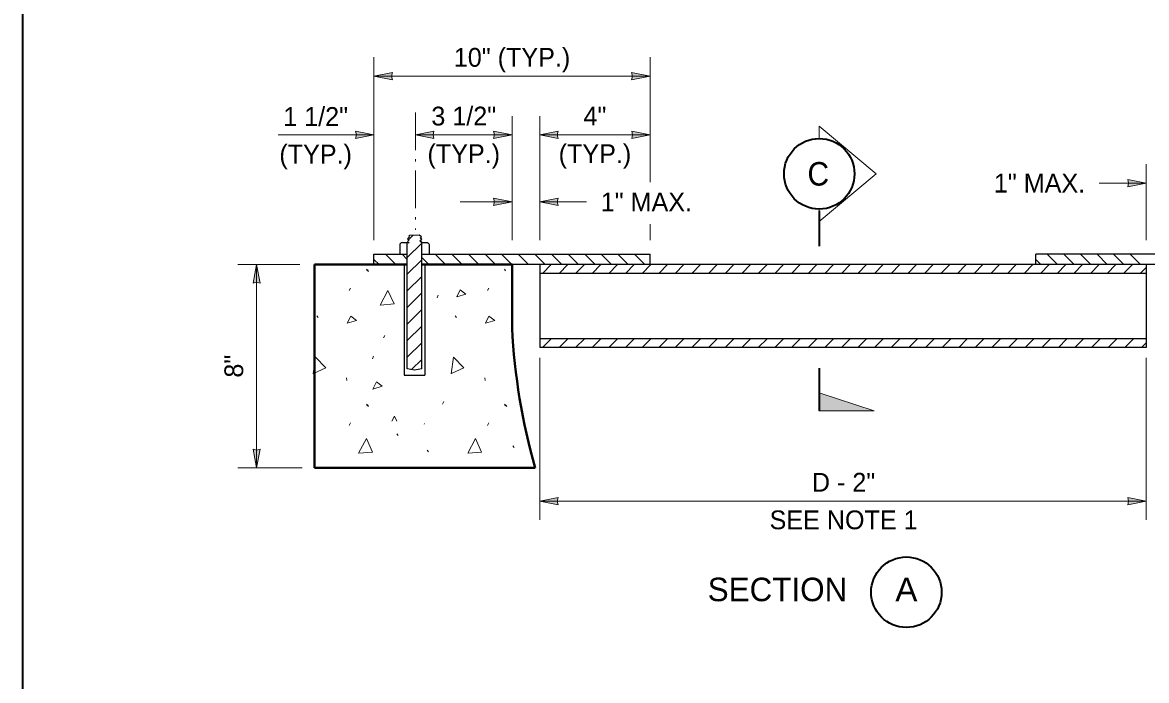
# Model space of a CAD drawing. Extents: x 99860 to 103153, y 99998 to 102077.
# Drawn here: x 99862 to 100819, y 100578 to 101138 of the extents above; entities that cross this region are included whole.
import ezdxf
from ezdxf.enums import TextEntityAlignment as Align

# ---------------------------------------------------------------- set-up
doc = ezdxf.new("R2010")
doc.units = 0
doc.header["$LTSCALE"] = 6.4
doc.linetypes.add('DOT_DASHED', pattern=[7.7, 5, -1.2, 0.3, -1.2])
for name, color, linetype, lineweight in [('1', 7, 'Continuous', 13), ('13', 7, 'Continuous', 40), ('15', 7, 'Continuous', 13), ('17', 7, 'Continuous', 13), ('18', 7, 'Continuous', 13), ('20', 7, 'Continuous', 13), ('9', 7, 'Continuous', 13)]:
    doc.layers.add(name, color=color, linetype=linetype, lineweight=lineweight)

msp = doc.modelspace()

# ---------------------------------------------------------------- hatches: boundary and pattern name
at = {"layer": '15'}
for points in [[(100161.332, 101092.323), (100177.057, 101089.239), (100176.329, 101092.323), (100177.057, 101095.407)], [(100396.492, 101092.323), (100380.767, 101089.239), (100381.495, 101092.323), (100380.767, 101095.407)], [(100161.332, 101042.323), (100145.607, 101039.239), (100146.335, 101042.323), (100145.607, 101045.407)], [(100196.622, 101042.323), (100212.347, 101039.239), (100211.619, 101042.323), (100212.347, 101045.407)], [(100278.942, 101042.323), (100263.217, 101039.239), (100263.945, 101042.323), (100263.217, 101045.407)], [(100302.472, 101042.323), (100318.197, 101039.239), (100317.469, 101042.323), (100318.197, 101045.407)], [(100396.562, 101042.323), (100380.837, 101039.239), (100381.565, 101042.323), (100380.837, 101045.407)], [(100818.992, 101001.29), (100803.267, 100998.206), (100803.995, 101001.29), (100803.267, 101004.374)], [(100278.942, 100985.29), (100263.217, 100982.206), (100263.945, 100985.29), (100263.217, 100988.374)], [(100302.472, 100985.29), (100318.197, 100982.206), (100317.469, 100985.29), (100318.197, 100988.374)], [(100061.397, 100931.954), (100064.481, 100916.229), (100061.397, 100916.957), (100058.313, 100916.229)], [(100061.397, 100759.144), (100058.313, 100774.869), (100061.397, 100774.141), (100064.481, 100774.869)], [(100302.472, 100730.814), (100318.197, 100727.73), (100317.469, 100730.814), (100318.197, 100733.898)], [(100818.992, 100730.814), (100803.267, 100727.73), (100803.995, 100730.814), (100803.267, 100733.898)]]:
    msp.add_hatch(color=256, dxfattribs=at).paths.add_polyline_path(points)
at = {"layer": '9'}
msp.add_hatch(color=256, dxfattribs=at).paths.add_polyline_path([(100540.533, 100822.948), (100587.415, 100807.423), (100540.533, 100807.423)])

# ---------------------------------------------------------------- linework, layer by layer
at = {"layer": '1', "lineweight": 25}
for p, q in [((100191.702, 100956.784), (100191.012, 100956.094)), ((100191.012, 100956.094), (100191.702, 100955.544)), ((100199.872, 100956.924), (100191.702, 100956.784)), ((100183.542, 100940.734), (100183.542, 100949.594)), ((100185.552, 100950.704), (100191.208, 100950.704)), ((100189.702, 100843.193), (100189.702, 100950.704)), ((100201.602, 100950.564), (100202.022, 100950.834)), ((100201.839, 100950.704), (100206.442, 100950.704)), ((100201.982, 100843.193), (100201.982, 100950.704)), ((100208.652, 100940.734), (100208.652, 100948.694)), ((100161.332, 100931.954), (100161.332, 100940.734)), ((100161.332, 100940.734), (100189.702, 100940.734)), ((100186.997, 100931.954), (100186.997, 100837.8)), ((100201.982, 100940.734), (100396.562, 100940.734)), ((100204.637, 100931.954), (100204.637, 100837.8)), ((100842.522, 100931.954), (100278.932, 100931.954)), ((100302.452, 100931.954), (100302.452, 100861.384)), ((100396.562, 100931.954), (100396.562, 100940.734)), ((100724.902, 100931.954), (100724.902, 100940.734)), ((100919.482, 100940.734), (100724.902, 100940.734)), ((100818.992, 100931.954), (100818.992, 100861.384)), ((100818.992, 100924.544), (100302.452, 100924.544)), ((100818.992, 100868.714), (100302.452, 100868.714)), ((100818.992, 100861.384), (100302.452, 100861.384)), ((100186.997, 100837.8), (100204.637, 100837.8))]:
    msp.add_line(p, q, dxfattribs=at)
at = {"layer": '1', "lineweight": 35}
msp.add_lwpolyline([(99862, 99999.5), (103151, 99999.5), (103151, 102075.5), (99862, 102075.5)], close=True, dxfattribs=at)
at = {"layer": '1', "lineweight": 25}
for points in [[(100191.702, 100955.544), (100189.772, 100953.954), (100191.292, 100953.184), (100189.772, 100951.744), (100191.432, 100950.634)], [(100202.022, 100950.834), (100200.422, 100952.084), (100201.952, 100953.534), (100200.562, 100954.364), (100201.672, 100955.544), (100199.872, 100956.924)], [(100201.982, 100843.193), (100195.842, 100842.229), (100189.702, 100843.193)]]:
    msp.add_lwpolyline(points, dxfattribs=at)
for centre, radius, start, end in [((100185.531, 100948.343), 2.325, 88.29585, 147.30365), ((100204.989, 100946.794), 4.132, 27.47168, 69.79443)]:
    msp.add_arc(centre, radius, start, end, dxfattribs=at)
at = {"layer": '13'}
for p, q in [((100110.717, 100931.954), (100110.717, 100759.144)), ((100110.717, 100931.954), (100189.702, 100931.954)), ((100201.982, 100931.954), (100278.942, 100931.954)), ((100278.942, 100931.954), (100278.942, 100877.934)), ((100110.717, 100759.144), (100298.559, 100759.144))]:
    msp.add_line(p, q, dxfattribs=at)
msp.add_arc((100811.964, 100904.944), 533.705, 182.90089, 195.85384, dxfattribs=at)
at = {"layer": '15'}
for p, q in [((100161.332, 101108.323), (100161.332, 100952.721)), ((100396.562, 101108.323), (100396.562, 101002.181)), ((100396.492, 101092.323), (100161.332, 101092.323)), ((100278.942, 101058.311), (100278.942, 100952.721)), ((100302.472, 101058.311), (100302.472, 100952.721)), ((100079.715, 101042.323), (100161.332, 101042.323)), ((100278.942, 101042.323), (100196.622, 101042.323)), ((100396.562, 101042.323), (100302.472, 101042.323)), ((100818.992, 101017.29), (100818.992, 100952.734)), ((100779.002, 101001.29), (100818.992, 101001.29)), ((100234.812, 100985.29), (100278.942, 100985.29)), ((100342.462, 100985.29), (100302.472, 100985.29)), ((100396.562, 100966.412), (100396.562, 100952.721)), ((100045.397, 100931.954), (100098.067, 100931.954)), ((100061.397, 100759.144), (100061.397, 100931.954)), ((100302.472, 100714.814), (100302.472, 100852.734)), ((100818.992, 100714.814), (100818.992, 100852.734)), ((100045.397, 100759.144), (100100.207, 100759.144)), ((100302.472, 100730.814), (100818.992, 100730.814))]:
    msp.add_line(p, q, dxfattribs=at)
at = {"layer": '15', "linetype": 'DOT_DASHED'}
msp.add_line((100196.622, 101061.347), (100196.622, 100961.494), dxfattribs=at)
at = {"layer": '15'}
for points in [[(100161.332, 101092.323), (100177.057, 101089.239), (100176.329, 101092.323), (100177.057, 101095.407)], [(100396.492, 101092.323), (100380.767, 101089.239), (100381.495, 101092.323), (100380.767, 101095.407)], [(100161.332, 101042.323), (100145.607, 101039.239), (100146.335, 101042.323), (100145.607, 101045.407)], [(100196.622, 101042.323), (100212.347, 101039.239), (100211.619, 101042.323), (100212.347, 101045.407)], [(100278.942, 101042.323), (100263.217, 101039.239), (100263.945, 101042.323), (100263.217, 101045.407)], [(100302.472, 101042.323), (100318.197, 101039.239), (100317.469, 101042.323), (100318.197, 101045.407)], [(100396.562, 101042.323), (100380.837, 101039.239), (100381.565, 101042.323), (100380.837, 101045.407)], [(100818.992, 101001.29), (100803.267, 100998.206), (100803.995, 101001.29), (100803.267, 101004.374)], [(100278.942, 100985.29), (100263.217, 100982.206), (100263.945, 100985.29), (100263.217, 100988.374)], [(100302.472, 100985.29), (100318.197, 100982.206), (100317.469, 100985.29), (100318.197, 100988.374)], [(100061.397, 100931.954), (100064.481, 100916.229), (100061.397, 100916.957), (100058.313, 100916.229)], [(100061.397, 100759.144), (100058.313, 100774.869), (100061.397, 100774.141), (100064.481, 100774.869)], [(100302.472, 100730.814), (100318.197, 100727.73), (100317.469, 100730.814), (100318.197, 100733.898)], [(100818.992, 100730.814), (100803.267, 100727.73), (100803.995, 100730.814), (100803.267, 100733.898)]]:
    msp.add_lwpolyline(points, close=True, dxfattribs=at)
at = {"layer": '17'}
for p, q in [((100154.832, 100928.004), (100155.802, 100926.554)), ((100155.802, 100927.454), (100156.762, 100926.004)), ((100272.512, 100928.004), (100273.482, 100926.554)), ((100140.302, 100909.814), (100141.272, 100912.024)), ((100215.022, 100903.654), (100215.992, 100905.864)), ((100257.982, 100909.814), (100259.022, 100912.024)), ((100112.772, 100888.434), (100113.742, 100886.984)), ((100230.522, 100888.434), (100231.482, 100886.984)), ((100169.562, 100869.544), (100170.542, 100871.764)), ((100159.952, 100851.834), (100160.922, 100854.054)), ((100138.022, 100835.574), (100138.302, 100833.364)), ((100255.772, 100835.574), (100255.982, 100833.364)), ((100154.832, 100813.234), (100155.802, 100811.774)), ((100155.802, 100812.684), (100156.762, 100811.224)), ((100219.662, 100813.234), (100220.702, 100815.444)), ((100272.512, 100813.234), (100273.482, 100811.774)), ((100273.482, 100812.684), (100274.452, 100811.224)), ((100140.302, 100795.034), (100141.272, 100797.244)), ((100204.022, 100796.144), (100204.372, 100796.904)), ((100257.982, 100795.034), (100259.022, 100797.244)), ((100180.926, 100787.958), (100181.896, 100786.508)), ((100206.759, 100774.048), (100207.729, 100772.598)), ((100279.628, 100777.692), (100280.598, 100776.242))]:
    msp.add_line(p, q, dxfattribs=at)
for points in [[(100166.592, 100897.494), (100173.232, 100910.014), (100178.422, 100898.534), (100166.872, 100897.494)], [(100109.512, 100839.174), (100111.452, 100853.214), (100120.242, 100844.154), (100109.722, 100839.244)], [(100227.202, 100839.174), (100229.132, 100853.214), (100237.992, 100844.154), (100227.472, 100839.244)], [(100176.552, 100798.704), (100178.902, 100803.134), (100180.912, 100798.704)], [(100148.269, 100771.432), (100154.909, 100783.952), (100160.029, 100772.472), (100148.479, 100771.432)], [(100241.223, 100771.432), (100247.863, 100783.952), (100252.983, 100772.472), (100241.433, 100771.432)]]:
    msp.add_lwpolyline(points, dxfattribs=at)
for points in [[(100231.762, 100904.484), (100234.672, 100910.574), (100239.582, 100906.904)], [(100138.572, 100882.074), (100141.542, 100888.154), (100146.462, 100884.494)], [(100256.322, 100882.074), (100259.232, 100888.154), (100264.142, 100884.494)], [(100160.432, 100826.034), (100163.412, 100832.114), (100168.322, 100828.454)]]:
    msp.add_lwpolyline(points, close=True, dxfattribs=at)
at = {"layer": '18'}
for p, q in [((100194.393, 100956.83), (100190.93, 100953.367)), ((100201.982, 100950.277), (100189.702, 100937.997)), ((100165.722, 100931.954), (100161.332, 100936.344)), ((100179.864, 100931.954), (100171.084, 100940.734)), ((100189.702, 100936.258), (100185.226, 100940.734)), ((100201.982, 100936.135), (100189.702, 100923.855)), ((100208.149, 100931.954), (100201.982, 100938.12)), ((100222.291, 100931.954), (100213.511, 100940.734)), ((100236.433, 100931.954), (100227.653, 100940.734)), ((100250.575, 100931.954), (100241.795, 100940.734)), ((100264.717, 100931.954), (100255.937, 100940.734)), ((100278.859, 100931.954), (100270.079, 100940.734)), ((100293.001, 100931.954), (100284.221, 100940.734)), ((100307.144, 100931.954), (100298.364, 100940.734)), ((100312.214, 100931.954), (100304.804, 100924.544)), ((100321.286, 100931.954), (100312.506, 100940.734)), ((100326.356, 100931.954), (100318.946, 100924.544)), ((100335.428, 100931.954), (100326.648, 100940.734)), ((100340.498, 100931.954), (100333.088, 100924.544)), ((100349.57, 100931.954), (100340.79, 100940.734)), ((100354.64, 100931.954), (100347.23, 100924.544)), ((100363.712, 100931.954), (100354.932, 100940.734)), ((100368.782, 100931.954), (100361.372, 100924.544)), ((100377.854, 100931.954), (100369.074, 100940.734)), ((100382.924, 100931.954), (100375.514, 100924.544)), ((100391.996, 100931.954), (100383.216, 100940.734)), ((100397.066, 100931.954), (100389.656, 100924.544)), ((100411.209, 100931.954), (100403.799, 100924.544)), ((100425.351, 100931.954), (100417.941, 100924.544)), ((100439.493, 100931.954), (100432.083, 100924.544)), ((100453.635, 100931.954), (100446.225, 100924.544)), ((100467.777, 100931.954), (100460.367, 100924.544)), ((100481.919, 100931.954), (100474.509, 100924.544)), ((100496.061, 100931.954), (100488.651, 100924.544)), ((100510.204, 100931.954), (100502.794, 100924.544)), ((100524.346, 100931.954), (100516.936, 100924.544)), ((100538.488, 100931.954), (100531.078, 100924.544)), ((100552.63, 100931.954), (100545.22, 100924.544)), ((100566.772, 100931.954), (100559.362, 100924.544)), ((100580.914, 100931.954), (100573.504, 100924.544)), ((100595.056, 100931.954), (100587.646, 100924.544)), ((100609.198, 100931.954), (100601.788, 100924.544)), ((100623.341, 100931.954), (100615.931, 100924.544)), ((100637.483, 100931.954), (100630.073, 100924.544)), ((100651.625, 100931.954), (100644.215, 100924.544)), ((100665.767, 100931.954), (100658.357, 100924.544)), ((100679.909, 100931.954), (100672.499, 100924.544)), ((100694.051, 100931.954), (100686.641, 100924.544)), ((100708.193, 100931.954), (100700.783, 100924.544)), ((100722.336, 100931.954), (100714.926, 100924.544)), ((100729.292, 100931.954), (100724.902, 100936.344)), ((100736.478, 100931.954), (100729.068, 100924.544)), ((100743.434, 100931.954), (100734.654, 100940.734)), ((100750.62, 100931.954), (100743.21, 100924.544)), ((100757.576, 100931.954), (100748.796, 100940.734)), ((100764.762, 100931.954), (100757.352, 100924.544)), ((100771.719, 100931.954), (100762.939, 100940.734)), ((100778.904, 100931.954), (100771.494, 100924.544)), ((100785.861, 100931.954), (100777.081, 100940.734)), ((100793.046, 100931.954), (100785.636, 100924.544)), ((100800.003, 100931.954), (100791.223, 100940.734)), ((100807.188, 100931.954), (100799.778, 100924.544)), ((100814.145, 100931.954), (100805.365, 100940.734)), ((100818.992, 100929.616), (100813.921, 100924.544)), ((100201.982, 100921.993), (100189.702, 100909.713)), ((100201.982, 100907.851), (100189.702, 100895.571)), ((100201.982, 100893.709), (100189.702, 100881.429)), ((100201.982, 100879.567), (100189.702, 100867.287)), ((100201.982, 100865.425), (100189.702, 100853.144)), ((100312.214, 100868.794), (100304.804, 100861.384)), ((100326.356, 100868.794), (100318.946, 100861.384)), ((100340.498, 100868.794), (100333.088, 100861.384)), ((100354.64, 100868.794), (100347.23, 100861.384)), ((100368.782, 100868.794), (100361.372, 100861.384)), ((100382.924, 100868.794), (100375.514, 100861.384)), ((100397.066, 100868.794), (100389.656, 100861.384)), ((100411.209, 100868.794), (100403.799, 100861.384)), ((100425.351, 100868.794), (100417.941, 100861.384)), ((100439.493, 100868.794), (100432.083, 100861.384)), ((100453.635, 100868.794), (100446.225, 100861.384)), ((100467.777, 100868.794), (100460.367, 100861.384)), ((100481.919, 100868.794), (100474.509, 100861.384)), ((100496.061, 100868.794), (100488.651, 100861.384)), ((100510.204, 100868.794), (100502.794, 100861.384)), ((100524.346, 100868.794), (100516.936, 100861.384)), ((100538.488, 100868.794), (100531.078, 100861.384)), ((100552.63, 100868.794), (100545.22, 100861.384)), ((100566.772, 100868.794), (100559.362, 100861.384)), ((100580.914, 100868.794), (100573.504, 100861.384)), ((100595.056, 100868.794), (100587.646, 100861.384)), ((100609.198, 100868.794), (100601.788, 100861.384)), ((100624.208, 100868.714), (100616.878, 100861.384)), ((100638.35, 100868.714), (100631.02, 100861.384)), ((100652.492, 100868.714), (100645.162, 100861.384)), ((100666.634, 100868.714), (100659.304, 100861.384)), ((100680.776, 100868.714), (100673.446, 100861.384)), ((100694.918, 100868.714), (100687.588, 100861.384)), ((100709.061, 100868.714), (100701.731, 100861.384)), ((100723.203, 100868.714), (100715.873, 100861.384)), ((100737.345, 100868.714), (100730.015, 100861.384)), ((100751.487, 100868.714), (100744.157, 100861.384)), ((100765.629, 100868.714), (100758.299, 100861.384)), ((100779.771, 100868.714), (100772.441, 100861.384)), ((100793.913, 100868.714), (100786.583, 100861.384)), ((100808.056, 100868.714), (100800.726, 100861.384)), ((100818.992, 100865.508), (100814.868, 100861.384)), ((100201.982, 100851.282), (100193.324, 100842.624))]:
    msp.add_line(p, q, dxfattribs=at)
at = {"layer": '9'}
msp.add_line((100540.531, 100968.63), (100540.531, 100979.231), dxfattribs=at)
at = {"layer": '9', "lineweight": 35}
for p, q in [((100540.532, 100977.668), (100540.532, 100947.668)), ((100540.532, 100843.948), (100540.532, 100807.424))]:
    msp.add_line(p, q, dxfattribs=at)
at = {"layer": '9'}
msp.add_lwpolyline([(100540.531, 101039.23), (100540.531, 101049.832), (100588.995, 101009.231), (100540.531, 100968.63)], dxfattribs=at)
msp.add_lwpolyline([(100540.533, 100822.948), (100587.415, 100807.423), (100540.533, 100807.423)], close=True, dxfattribs=at)
at = {"layer": '9', "lineweight": 35}
for centre in [(100540.532, 101009.231), (100614.738, 100653.232)]:
    msp.add_circle(centre, 30, dxfattribs=at)
at = {"layer": '9'}
msp.add_arc((100540.532, 101009.231), 30, 269.99779, 90.00221, dxfattribs=at)

# ---------------------------------------------------------------- texts
at = {"layer": '20'}
for s, p in [('10" (TYP.)', (100278.914, 101100.323)), ('1 1/2"', (100111.663, 101049.981)), ('3 1/2"', (100237.785, 101050.323)), ('4"', (100349.519, 101050.323)), ('(TYP.)', (100111.662, 101017.981)), ('(TYP.)', (100237.785, 101018.323)), ('(TYP.)', (100349.519, 101018.323)), ('D - 2"', (100561.252, 100738.814)), ('SEE NOTE 1', (100561.252, 100706.814))]:
    msp.add_text(s, height=16, dxfattribs=at).set_placement(p, align=Align.CENTER)
for s, width, p in [('C', 0.95, (100539.698, 100999.212)), ('A', 1.05, (100614.743, 100645.613))]:
    msp.add_text(s, height=20, dxfattribs=dict(at, width=width)).set_placement(p, align=Align.CENTER)
for p in [(100689.25, 100993.29), (100354.462, 100977.29)]:
    msp.add_text('1" MAX.', height=16, dxfattribs=at).set_placement(p)
msp.add_text('8"', height=16, rotation=90, dxfattribs=at).set_placement((100049.952, 100845.551), align=Align.CENTER)
msp.add_text('SECTION', height=20, dxfattribs=at).set_placement((100564.417, 100645.614), align=Align.RIGHT)

doc.saveas('drawing.dxf')
